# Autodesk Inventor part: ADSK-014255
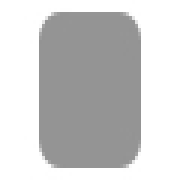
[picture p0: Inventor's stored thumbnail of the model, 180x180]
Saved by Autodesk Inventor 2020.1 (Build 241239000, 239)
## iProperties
Created: 2019-01
Part Number: ADSK-014255
Material: Stahl, weich
Document SubType Name: Modeling
Designer: lutzd
Language: de-DE
Size Designation: 5 x 89,384472 x 39,384472
Categories: <MemberInstance><Categories><Category DisplayName="Sonstige Bauteile" InternalName="5aa15e00-363f-49f2-933f-16f664388e3f" Mnemonic="OTHER"><Category DisplayName
Mass: 137.332 g
Surface Area: 82.4257 cm^2
Volume: 17.4945 cm^3
Density: 7.85 g/cm^3
Appearance: Semi-Polished(8)
Dimensions: 39,4x89,4x5 mm
Mass: 0,137 kg
DocNumber: ADSK-014255
Folder: 01 - Themengebiete\Simplification\01 - Packaging machine\ADSK-014200\Frame\
VDS_Category: 3D Komponenten
VDS_NumSchm: Autodesk
IsCustomPart: 1
Title: end cap
Author: lutzd
Revision Number: -
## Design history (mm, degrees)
sketch "Sketch1"
  geometry: L1 (0, 20.175)-(0, -21.446); L2 (-20.203, 0)-(20.169, 0); L3 (-19.692, 44.692)-(19.692, 44.692); L4 (19.692, 44.692)-(19.692, -44.692); L5 (19.692, -44.692)-(-19.692, -44.692); L6 (-19.692, -44.692)-(-19.692, 44.692); 1 further point
  constraints: 12 end point, 2 horizontal, 2 parallel, 2 point on line, 1 perpendicular, 1 vertical
  dimensions: "d0" = 89.38447 distance between parallel lines of L5 L3 (= height); "d1" = 44.69224 distance between parallel lines of L2 L3 (= 0.5 x height); "d2" = 39.38447 distance between parallel lines of L6 L4 (= width); "d3" = 19.69224 distance between parallel lines of L6 L1 (= 0.5 x width)
extrude "Extrusion1" new body sketch "Sketch1" distance "d4" = 5 (= thickness); taper "d5" = 0 deg
fillet "Fillet1" dims "d6" = 5 (= fillet), "d7" = 0, "fillet" = 5 [user parameter; used in 1 equation term]
chamfer "Chamfer1" distance "d8" = 0 (computed from chamfer); stored, may be unused: second distance "d9" = 2, angle "d10" = 45 deg; dims "d11" = 0, "chamfer" = 0 [user parameter; used in 1 equation term]
body "Solid1"
other parameters: "thickness" = 5 [user parameter; used in 1 equation term], "width" = 39.38447 [user parameter; used in 2 equation terms], "height" = 89.38447 [user parameter; used in 2 equation terms]
